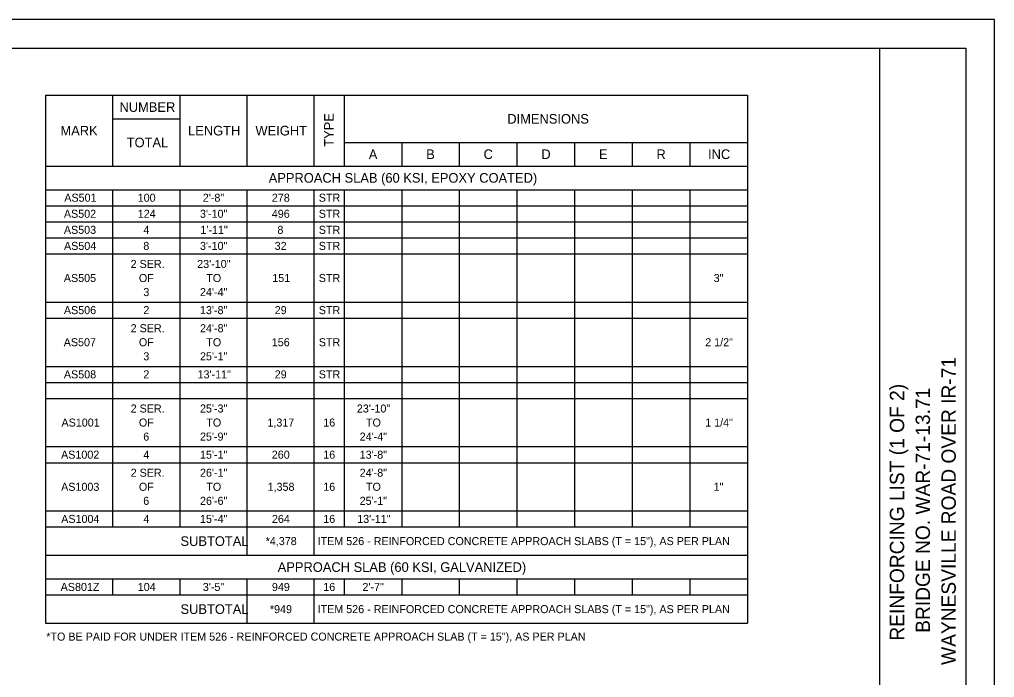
# Model space of a CAD drawing. Extents: x 0 to 34, y 0 to 22.
# Drawn here: x 17 to 34, y 10.53 to 22 of the extents above; entities that cross this region are included whole.
import ezdxf

# ---------------------------------------------------------------- set-up
doc = ezdxf.new("R2010")
doc.units = 0
for name, color, linetype in [('Default', 7, 'Continuous'), ('SH_Border', 7, 'Continuous'), ('SH_Cut_Line', 7, 'Continuous'), ('SH_Data', 7, 'Continuous')]:
    doc.layers.add(name, color=color, linetype=linetype)

msp = doc.modelspace()

# ---------------------------------------------------------------- linework, layer by layer
at = {"layer": 'Default'}
for p, q in [((17.454, 20.68), (29.692, 20.68)), ((17.454, 20.68), (17.454, 11.473)), ((18.624, 20.68), (18.624, 19.445)), ((19.793, 20.68), (19.793, 19.445)), ((20.962, 20.68), (20.962, 19.445)), ((22.132, 20.68), (22.132, 19.445)), ((22.659, 20.68), (22.659, 19.445)), ((29.692, 20.68), (29.692, 11.473)), ((18.624, 20.268), (19.793, 20.268)), ((22.659, 19.856), (29.692, 19.856)), ((23.664, 19.856), (23.664, 19.445)), ((24.668, 19.856), (24.668, 19.445)), ((25.673, 19.856), (25.673, 19.445)), ((26.678, 19.856), (26.678, 19.445)), ((27.682, 19.856), (27.682, 19.445)), ((28.687, 19.856), (28.687, 19.445)), ((17.454, 19.445), (29.692, 19.445)), ((17.454, 19.033), (29.692, 19.033)), ((18.624, 19.033), (18.624, 13.153)), ((19.793, 19.033), (19.793, 13.153)), ((20.962, 19.033), (20.962, 12.659)), ((22.132, 19.033), (22.132, 12.659)), ((22.659, 19.033), (22.659, 13.153)), ((23.664, 19.033), (23.664, 13.153)), ((24.668, 19.033), (24.668, 13.153)), ((25.673, 19.033), (25.673, 13.153)), ((26.678, 19.033), (26.678, 13.153)), ((27.682, 19.033), (27.682, 13.153)), ((28.687, 19.033), (28.687, 13.153)), ((17.454, 18.753), (29.692, 18.753)), ((17.454, 18.473), (29.692, 18.473)), ((17.454, 18.193), (29.692, 18.193)), ((17.454, 17.913), (29.692, 17.913)), ((17.454, 17.073), (29.692, 17.073)), ((17.454, 16.793), (29.692, 16.793)), ((17.454, 15.953), (29.692, 15.953)), ((17.454, 15.673), (29.692, 15.673)), ((17.454, 15.393), (29.692, 15.393)), ((17.454, 14.553), (29.692, 14.553)), ((17.454, 14.273), (29.692, 14.273)), ((17.454, 13.433), (29.692, 13.433)), ((17.454, 13.153), (29.692, 13.153)), ((17.454, 12.659), (29.692, 12.659)), ((17.454, 12.247), (29.692, 12.247)), ((18.624, 12.247), (18.624, 11.967)), ((19.793, 12.247), (19.793, 11.967)), ((20.962, 12.247), (20.962, 11.473)), ((22.132, 12.247), (22.132, 11.473)), ((22.659, 12.247), (22.659, 11.967)), ((23.664, 12.247), (23.664, 11.967)), ((24.668, 12.247), (24.668, 11.967)), ((25.673, 12.247), (25.673, 11.967)), ((26.678, 12.247), (26.678, 11.967)), ((27.682, 12.247), (27.682, 11.967)), ((28.687, 12.247), (28.687, 11.967)), ((17.454, 11.967), (29.692, 11.967)), ((17.454, 11.473), (29.692, 11.473))]:
    msp.add_line(p, q, dxfattribs=at)
at = {"layer": 'SH_Border'}
msp.add_line((32, 0.5), (32, 21.5), dxfattribs=at)
msp.add_lwpolyline([(1.5, 21.5), (33.5, 21.5), (33.5, 0.5), (1.5, 0.5)], close=True, dxfattribs=at)
at = {"layer": 'SH_Cut_Line'}
msp.add_lwpolyline([(0, 0), (34, 0), (34, 22), (0, 22)], close=True, dxfattribs=at)

# ---------------------------------------------------------------- texts
at = {"layer": 'Default'}
for s, height, p in [('NUMBER', 0.168, (18.743, 20.39)), ('DIMENSIONS', 0.168, (25.505, 20.184)), ('MARK', 0.168, (17.714, 19.978)), ('LENGTH', 0.168, (19.939, 19.978)), ('WEIGHT', 0.168, (21.114, 19.978)), ('TOTAL', 0.168, (18.869, 19.772)), ('A', 0.168, (23.09, 19.567)), ('B', 0.168, (24.091, 19.567)), ('C', 0.168, (25.092, 19.567)), ('D', 0.168, (26.099, 19.567)), ('E', 0.168, (27.104, 19.567)), ('R', 0.168, (28.106, 19.567)), ('INC', 0.168, (29.005, 19.567)), ('APPROACH SLAB (60 KSI, EPOXY COATED)', 0.168, (21.345, 19.155)), ('AS501', 0.14, (17.781, 18.823)), ('100', 0.14, (19.061, 18.823)), ('2\'-8"', 0.14, (20.196, 18.823)), ('278', 0.14, (21.4, 18.823)), ('STR', 0.14, (22.219, 18.823)), ('AS502', 0.14, (17.774, 18.543)), ('124', 0.14, (19.062, 18.543)), ('3\'-10"', 0.14, (20.147, 18.543)), ('496', 0.14, (21.399, 18.543)), ('STR', 0.14, (22.219, 18.543)), ('AS503', 0.14, (17.774, 18.263)), ('4', 0.14, (19.16, 18.263)), ('1\'-11"', 0.14, (20.154, 18.263)), ('8', 0.14, (21.497, 18.263)), ('STR', 0.14, (22.219, 18.263)), ('AS504', 0.14, (17.776, 17.983)), ('8', 0.14, (19.159, 17.983)), ('3\'-10"', 0.14, (20.147, 17.983)), ('32', 0.14, (21.449, 17.983)), ('STR', 0.14, (22.219, 17.983)), ('2 SER.', 0.14, (18.938, 17.668)), ('23\'-10"', 0.14, (20.098, 17.668)), ('AS505', 0.14, (17.773, 17.423)), ('OF', 0.14, (19.082, 17.423)), ('TO', 0.14, (20.257, 17.423)), ('151', 0.14, (21.407, 17.423)), ('STR', 0.14, (22.219, 17.423)), ('3"', 0.14, (29.103, 17.423)), ('3', 0.14, (19.159, 17.178)), ('24\'-4"', 0.14, (20.147, 17.178)), ('AS506', 0.14, (17.774, 16.863)), ('2', 0.14, (19.159, 16.863)), ('13\'-8"', 0.14, (20.147, 16.863)), ('29', 0.14, (21.45, 16.863)), ('STR', 0.14, (22.219, 16.863)), ('2 SER.', 0.14, (18.938, 16.548)), ('24\'-8"', 0.14, (20.147, 16.548)), ('AS507', 0.14, (17.771, 16.303)), ('OF', 0.14, (19.082, 16.303)), ('TO', 0.14, (20.257, 16.303)), ('156', 0.14, (21.399, 16.303)), ('STR', 0.14, (22.219, 16.303)), ('2 1/2"', 0.14, (28.956, 16.303)), ('3', 0.14, (19.159, 16.058)), ('25\'-1"', 0.14, (20.147, 16.058)), ('AS508', 0.14, (17.774, 15.743)), ('2', 0.14, (19.159, 15.743)), ('13\'-11"', 0.14, (20.105, 15.743)), ('29', 0.14, (21.45, 15.743)), ('STR', 0.14, (22.219, 15.743)), ('2 SER.', 0.14, (18.938, 15.148)), ('25\'-3"', 0.14, (20.147, 15.148)), ('23\'-10"', 0.14, (22.882, 15.148)), ('AS1001', 0.14, (17.732, 14.903)), ('OF', 0.14, (19.082, 14.903)), ('TO', 0.14, (20.257, 14.903)), ('1,317', 0.14, (21.323, 14.903)), ('16', 0.14, (22.296, 14.903)), ('TO', 0.14, (23.041, 14.903)), ('1 1/4"', 0.14, (28.956, 14.903)), ('6', 0.14, (19.158, 14.658)), ('25\'-9"', 0.14, (20.147, 14.658)), ('24\'-4"', 0.14, (22.931, 14.658)), ('AS1002', 0.14, (17.725, 14.343)), ('4', 0.14, (19.16, 14.343)), ('15\'-1"', 0.14, (20.147, 14.343)), ('260', 0.14, (21.399, 14.343)), ('16', 0.14, (22.296, 14.343)), ('13\'-8"', 0.14, (22.931, 14.343)), ('2 SER.', 0.14, (18.938, 14.028)), ('26\'-1"', 0.14, (20.147, 14.028)), ('24\'-8"', 0.14, (22.931, 14.028)), ('AS1003', 0.14, (17.726, 13.783)), ('OF', 0.14, (19.082, 13.783)), ('TO', 0.14, (20.257, 13.783)), ('1,358', 0.14, (21.326, 13.783)), ('16', 0.14, (22.296, 13.783)), ('TO', 0.14, (23.041, 13.783)), ('1"', 0.14, (29.103, 13.783)), ('6', 0.14, (19.158, 13.538)), ('26\'-6"', 0.14, (20.147, 13.538)), ('25\'-1"', 0.14, (22.931, 13.538)), ('AS1004', 0.14, (17.727, 13.223)), ('4', 0.14, (19.16, 13.223)), ('15\'-4"', 0.14, (20.147, 13.223)), ('264', 0.14, (21.401, 13.223)), ('16', 0.14, (22.296, 13.223)), ('13\'-11"', 0.14, (22.888, 13.223)), ('SUBTOTAL', 0.168, (19.807, 12.822)), ('*4,378', 0.14, (21.292, 12.836)), ('ITEM 526 - REINFORCED CONCRETE APPROACH SLABS (T = 15"), AS PER PLAN', 0.14, (22.198, 12.836)), ('APPROACH SLAB (60 KSI, GALVANIZED)', 0.168, (21.502, 12.369)), ('AS801Z', 0.14, (17.718, 12.037)), ('104', 0.14, (19.062, 12.037)), ('3\'-5"', 0.14, (20.196, 12.037)), ('949', 0.14, (21.401, 12.037)), ('16', 0.14, (22.296, 12.037)), ('2\'-7"', 0.14, (22.98, 12.037)), ('SUBTOTAL', 0.168, (19.807, 11.636)), ('*949', 0.14, (21.366, 11.65)), ('ITEM 526 - REINFORCED CONCRETE APPROACH SLABS (T = 15"), AS PER PLAN', 0.14, (22.198, 11.65)), ('*TO BE PAID FOR UNDER ITEM 526 - REINFORCED CONCRETE APPROACH SLAB (T = 15"), AS PER PLAN', 0.14, (17.467, 11.171))]:
    msp.add_text(s, height=height, dxfattribs=at).set_placement(p)
msp.add_text('TYPE', height=0.168, rotation=90, dxfattribs=at).set_placement((22.479, 19.781))
at = {"layer": 'SH_Data'}
for s, p in [('WAYNESVILLE ROAD OVER IR-71', (33.325, 10.747)), ('REINFORCING LIST (1 OF 2)', (32.425, 11.171)), ('BRIDGE NO. WAR-71-13.71', (32.875, 11.307))]:
    msp.add_text(s, height=0.25, rotation=90, dxfattribs=at).set_placement(p)

doc.saveas('drawing.dxf')
